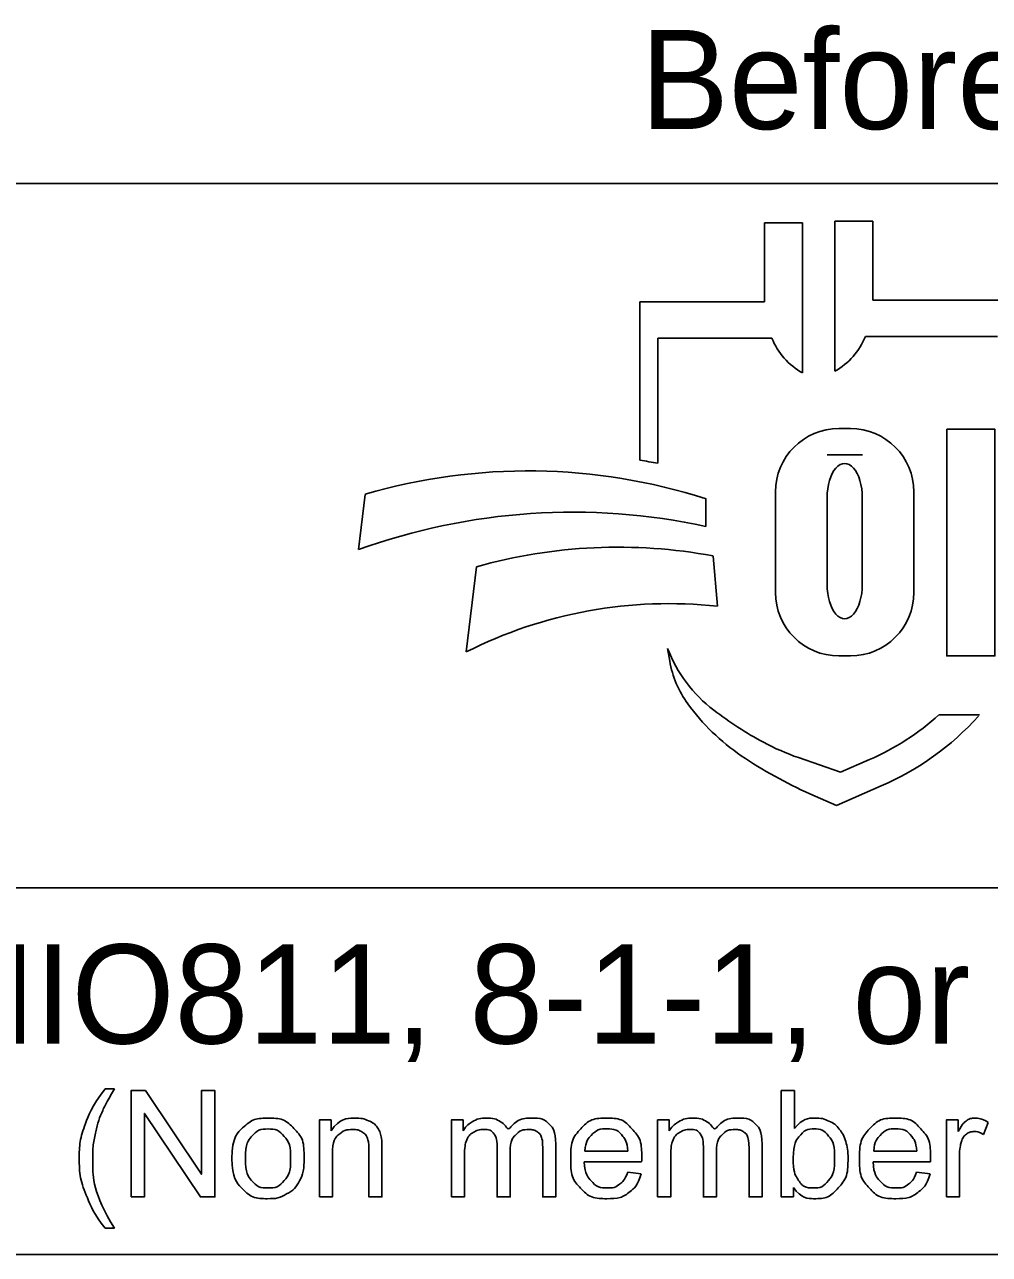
# Model space of a CAD drawing. Extents: x -7.5 to 26.5, y 3.5 to 25.5.
# Drawn here: x -4.768 to -3.406, y 5.643 to 7.38 of the extents above; entities that cross this region are included whole.
import ezdxf

# ---------------------------------------------------------------- set-up
doc = ezdxf.new("R2010")
doc.units = 0
doc.layers.add('SH_Data', color=7, linetype='Continuous')
doc.layers.add('SH_Text', color=7, linetype='Continuous')

msp = doc.modelspace()

# ---------------------------------------------------------------- linework, layer by layer
at = {"layer": 'SH_Data'}
for p, q in [((-5.0794, 7.1553), (-0.8294, 7.1553)), ((-0.8294, 6.1607), (-5.0794, 6.1607)), ((-0.8294, 5.6428), (-5.0794, 5.6428))]:
    msp.add_line(p, q, dxfattribs=at)
at = {"layer": 'SH_Text'}
for p, q in [((-3.7234, 6.9883), (-3.7234, 7.0998)), ((-3.7234, 7.0998), (-3.6698, 7.0998)), ((-3.6698, 7.0998), (-3.6698, 6.8877)), ((-3.6241, 6.89), (-3.6241, 7.1021)), ((-3.6241, 7.1021), (-3.5705, 7.1021)), ((-3.5705, 7.1021), (-3.5705, 6.9906)), ((-3.8994, 6.7644), (-3.8994, 6.9883)), ((-3.8994, 6.9883), (-3.7234, 6.9883)), ((-3.5705, 6.9906), (-3.3712, 6.9906)), ((-3.8741, 6.9369), (-3.8741, 6.76)), ((-3.713, 6.9369), (-3.8741, 6.9369)), ((-3.3945, 6.9392), (-3.5809, 6.9392)), ((-3.6184, 6.8091), (-3.6019, 6.8091)), ((-3.5851, 6.7721), (-3.6349, 6.7721)), ((-4.2967, 6.6381), (-4.2873, 6.7162)), ((-3.8061, 6.7097), (-3.8061, 6.6709)), ((-3.7079, 6.5776), (-3.7079, 6.7196)), ((-3.635, 6.589), (-3.635, 6.7114)), ((-3.5852, 6.7114), (-3.5852, 6.589)), ((-3.5124, 6.7196), (-3.5124, 6.5776)), ((-3.7961, 6.6291), (-3.7899, 6.5582)), ((-4.1449, 6.4936), (-4.1302, 6.6137)), ((-3.8572, 6.4807), (-3.8603, 6.4986)), ((-3.6019, 6.4882), (-3.6184, 6.4882)), ((-3.4769, 6.4048), (-3.4195, 6.4048)), ((-3.6753, 6.3444), (-3.6159, 6.3239)), ((-3.6159, 6.3239), (-3.5749, 6.3417)), ((-3.6219, 6.2769), (-3.6593, 6.2934)), ((-3.5587, 6.3044), (-3.6219, 6.2769))]:
    msp.add_line(p, q, dxfattribs=at)
msp.add_lwpolyline([(-3.466, 6.8081), (-3.398, 6.8081), (-3.398, 6.4881), (-3.466, 6.4881)], close=True, dxfattribs=at)
for points in [[(-4.6548, 5.8766), (-4.6416, 5.8766)], [(-4.6181, 5.7239), (-4.6181, 5.8741), (-4.5977, 5.8741), (-4.5187, 5.7561), (-4.5187, 5.8741), (-4.4997, 5.8741), (-4.4997, 5.7239), (-4.5201, 5.7239), (-4.5991, 5.8419), (-4.5991, 5.7239), (-4.6181, 5.7239)], [(-3.6826, 5.7239), (-3.6997, 5.7239), (-3.6997, 5.8741), (-3.6812, 5.8741), (-3.6812, 5.8206)], [(-4.3521, 5.7239), (-4.3521, 5.8328), (-4.3355, 5.8328), (-4.3355, 5.8173)], [(-4.1657, 5.7239), (-4.1657, 5.8328), (-4.1492, 5.8328), (-4.1492, 5.8174)], [(-3.8743, 5.7239), (-3.8743, 5.8328), (-3.8578, 5.8328), (-3.8578, 5.8174)], [(-3.4665, 5.7239), (-3.4665, 5.8328), (-3.4499, 5.8328), (-3.4499, 5.8163)], [(-3.4075, 5.8293), (-3.4139, 5.8122)], [(-4.2637, 5.7908), (-4.2637, 5.7239), (-4.2822, 5.7239), (-4.2822, 5.7901)], [(-4.0826, 5.7871), (-4.0826, 5.7239), (-4.101, 5.7239), (-4.101, 5.7946)], [(-4.0182, 5.7986), (-4.0182, 5.7239), (-4.0366, 5.7239), (-4.0366, 5.7924)], [(-3.9771, 5.7887), (-3.9163, 5.7887)], [(-3.7912, 5.7871), (-3.7912, 5.7239), (-3.8097, 5.7239), (-3.8097, 5.7946)], [(-3.7268, 5.7986), (-3.7268, 5.7239), (-3.7452, 5.7239), (-3.7452, 5.7924)], [(-3.5691, 5.7887), (-3.5083, 5.7887)], [(-4.3337, 5.7833), (-4.3337, 5.7239), (-4.3521, 5.7239)], [(-4.1473, 5.7803), (-4.1473, 5.7239), (-4.1657, 5.7239)], [(-3.8969, 5.7736), (-3.9781, 5.7736)], [(-3.8559, 5.7803), (-3.8559, 5.7239), (-3.8743, 5.7239)], [(-3.489, 5.7736), (-3.5701, 5.7736)], [(-3.4481, 5.7809), (-3.4481, 5.7239), (-3.4665, 5.7239)], [(-3.9165, 5.7591), (-3.8975, 5.7567)], [(-3.5085, 5.7591), (-3.4895, 5.7567)], [(-3.6826, 5.7375), (-3.6826, 5.7239)], [(-4.6416, 5.6798), (-4.6548, 5.6798)]]:
    msp.add_lwpolyline(points, dxfattribs=at)
for centre, radius, start, end in [((-3.6216, 6.9736), 0.0985, 201.9296, 240.7469), ((-3.6722, 6.976), 0.0985, 299.2531, 338.0704), ((-3.6184, 6.7196), 0.0895, 90, 180), ((-3.6019, 6.7196), 0.0895, 0, 90), ((-4.0275, 5.9554), 0.8191, 79.2074, 81.0007), ((-4.0572, 5.9302), 0.8191, 72.1402, 106.3144), ((-3.9942, 5.7991), 0.8919, 77.8238, 109.8274), ((-3.9303, 5.9094), 0.7322, 79.44, 105.8467), ((-3.6184, 6.5776), 0.0895, 180, 270), ((-3.6019, 6.5776), 0.0895, 270, 0), ((-3.8582, 5.9262), 0.6357, 83.8248, 116.8021), ((-3.6729, 6.5707), 0.2008, 201.0457, 232.5314), ((-3.7159, 6.5048), 0.1433, 189.6817, 216.0884), ((-3.5822, 6.6022), 0.3088, 216.0884, 235.7167), ((-3.4803, 6.8219), 0.5173, 232.5314, 241.794), ((-3.7183, 6.6722), 0.3602, 293.4582, 312.0712), ((-3.7183, 6.6722), 0.401, 293.4582, 317.8286), ((-3.5655, 6.6631), 0.3371, 241.794, 250.9821), ((-3.4157, 6.8465), 0.6044, 235.7167, 246.2325)]:
    msp.add_arc(centre, radius, start, end, dxfattribs=at)
for centre, start_param, end_param in [((-3.6101, 6.7114), 4.712389, 7.853982), ((-3.6101, 6.589), 1.570796, 4.712389)]:
    msp.add_ellipse(centre, major_axis=(0, 0.0484), ratio=0.514403, start_param=start_param, end_param=end_param, dxfattribs=at)
for points in [[(-4.6548, 5.6798), (-4.6701, 5.699), (-4.6806, 5.7248), (-4.6912, 5.7506), (-4.6912, 5.7783), (-4.6912, 5.8026), (-4.6833, 5.825), (-4.6741, 5.8509), (-4.6548, 5.8766)], [(-4.6416, 5.8766), (-4.654, 5.8553), (-4.658, 5.8462), (-4.6642, 5.832), (-4.6678, 5.8167), (-4.6722, 5.7975), (-4.6722, 5.7782), (-4.6722, 5.7289), (-4.6416, 5.6798)], [(-4.4756, 5.7783), (-4.4756, 5.8085), (-4.4588, 5.8231), (-4.4448, 5.8352), (-4.4246, 5.8352), (-4.4022, 5.8352), (-4.388, 5.8205), (-4.3737, 5.8058), (-4.3737, 5.7799), (-4.3737, 5.7589), (-4.38, 5.7469), (-4.3863, 5.7348), (-4.3983, 5.7282), (-4.4104, 5.7215), (-4.4246, 5.7215), (-4.4474, 5.7215), (-4.4615, 5.7362), (-4.4756, 5.7508), (-4.4756, 5.7783)], [(-4.4566, 5.7783), (-4.4566, 5.7574), (-4.4475, 5.747), (-4.4384, 5.7366), (-4.4246, 5.7366), (-4.4109, 5.7366), (-4.4018, 5.7471), (-4.3927, 5.7575), (-4.3927, 5.779), (-4.3927, 5.7991), (-4.4019, 5.8095), (-4.411, 5.8199), (-4.4246, 5.8199), (-4.4384, 5.8199), (-4.4475, 5.8096), (-4.4566, 5.7992), (-4.4566, 5.7783)], [(-4.3355, 5.8173), (-4.3235, 5.8352), (-4.3009, 5.8352), (-4.2911, 5.8352), (-4.2828, 5.8316), (-4.2746, 5.8281), (-4.2705, 5.8224), (-4.2664, 5.8166), (-4.2648, 5.8087), (-4.2637, 5.8036), (-4.2637, 5.7908)], [(-4.2822, 5.7901), (-4.2822, 5.8013), (-4.2843, 5.8069), (-4.2865, 5.8125), (-4.292, 5.8158), (-4.2974, 5.8191), (-4.3048, 5.8191), (-4.3166, 5.8191), (-4.3251, 5.8117), (-4.3337, 5.8042), (-4.3337, 5.7833)], [(-4.1492, 5.8174), (-4.1441, 5.8254), (-4.1356, 5.8303), (-4.1271, 5.8352), (-4.1162, 5.8352), (-4.1041, 5.8352), (-4.0964, 5.8301), (-4.0886, 5.8251), (-4.0855, 5.8161), (-4.0725, 5.8352), (-4.0518, 5.8352), (-4.0356, 5.8352), (-4.0269, 5.8262), (-4.0182, 5.8172), (-4.0182, 5.7986)], [(-4.101, 5.7946), (-4.101, 5.8069), (-4.1055, 5.813), (-4.1101, 5.8191), (-4.1203, 5.8191), (-4.1281, 5.8191), (-4.1347, 5.815), (-4.1413, 5.811), (-4.1443, 5.8031), (-4.1473, 5.7952), (-4.1473, 5.7803)], [(-4.0366, 5.7924), (-4.0366, 5.8035), (-4.0384, 5.8083), (-4.0402, 5.8132), (-4.0449, 5.8162), (-4.0496, 5.8191), (-4.056, 5.8191), (-4.0674, 5.8191), (-4.075, 5.8115), (-4.0826, 5.8039), (-4.0826, 5.7871)], [(-3.8975, 5.7567), (-3.902, 5.74), (-3.9141, 5.7307), (-3.9263, 5.7215), (-3.9453, 5.7215), (-3.9691, 5.7215), (-3.9831, 5.7362), (-3.9971, 5.7509), (-3.9971, 5.7774), (-3.9971, 5.8049), (-3.983, 5.82), (-3.9688, 5.8352), (-3.9463, 5.8352), (-3.9245, 5.8352), (-3.9107, 5.8203), (-3.8968, 5.8055), (-3.8968, 5.7785), (-3.8968, 5.7769), (-3.8969, 5.7736)], [(-3.9163, 5.7887), (-3.9175, 5.8025), (-3.9233, 5.8094), (-3.9321, 5.8201), (-3.9461, 5.8201), (-3.9588, 5.8201), (-3.9675, 5.8115), (-3.9761, 5.803), (-3.9771, 5.7887)], [(-3.8578, 5.8174), (-3.8527, 5.8254), (-3.8442, 5.8303), (-3.8357, 5.8352), (-3.8248, 5.8352), (-3.8127, 5.8352), (-3.805, 5.8301), (-3.7973, 5.8251), (-3.7941, 5.8161), (-3.7812, 5.8352), (-3.7604, 5.8352), (-3.7442, 5.8352), (-3.7355, 5.8262), (-3.7268, 5.8172), (-3.7268, 5.7986)], [(-3.8097, 5.7946), (-3.8097, 5.8069), (-3.8142, 5.813), (-3.8187, 5.8191), (-3.8289, 5.8191), (-3.8367, 5.8191), (-3.8433, 5.815), (-3.8499, 5.811), (-3.8529, 5.8031), (-3.8559, 5.7952), (-3.8559, 5.7803)], [(-3.7452, 5.7924), (-3.7452, 5.8035), (-3.747, 5.8083), (-3.7488, 5.8132), (-3.7535, 5.8162), (-3.7582, 5.8191), (-3.7646, 5.8191), (-3.7761, 5.8191), (-3.7836, 5.8115), (-3.7912, 5.8039), (-3.7912, 5.7871)], [(-3.6828, 5.7792), (-3.6828, 5.7596), (-3.6775, 5.7509), (-3.6688, 5.7366), (-3.654, 5.7366), (-3.6419, 5.7366), (-3.6331, 5.7471), (-3.6244, 5.7576), (-3.6244, 5.7784), (-3.6244, 5.7998), (-3.6328, 5.8099), (-3.6412, 5.8201), (-3.6532, 5.8201), (-3.6652, 5.8201), (-3.674, 5.8096), (-3.6828, 5.799), (-3.6828, 5.7792)], [(-3.6812, 5.8206), (-3.6696, 5.8352), (-3.6514, 5.8352), (-3.6414, 5.8352), (-3.6324, 5.8311), (-3.6235, 5.8271), (-3.6177, 5.8198), (-3.6119, 5.8124), (-3.6086, 5.8021), (-3.6054, 5.7918), (-3.6054, 5.78), (-3.6054, 5.752), (-3.6192, 5.7368), (-3.633, 5.7215), (-3.6524, 5.7215), (-3.6716, 5.7215), (-3.6826, 5.7375)], [(-3.4895, 5.7567), (-3.494, 5.74), (-3.5062, 5.7307), (-3.5183, 5.7215), (-3.5373, 5.7215), (-3.5611, 5.7215), (-3.5751, 5.7362), (-3.5891, 5.7509), (-3.5891, 5.7774), (-3.5891, 5.8049), (-3.575, 5.82), (-3.5608, 5.8352), (-3.5383, 5.8352), (-3.5165, 5.8352), (-3.5027, 5.8203), (-3.4889, 5.8055), (-3.4889, 5.7785), (-3.4889, 5.7769), (-3.489, 5.7736)], [(-3.5083, 5.7887), (-3.5095, 5.8025), (-3.5153, 5.8094), (-3.5241, 5.8201), (-3.5381, 5.8201), (-3.5508, 5.8201), (-3.5595, 5.8115), (-3.5682, 5.803), (-3.5691, 5.7887)], [(-3.4499, 5.8163), (-3.4436, 5.8278), (-3.4382, 5.8315), (-3.4329, 5.8352), (-3.4264, 5.8352), (-3.4171, 5.8352), (-3.4075, 5.8293)], [(-3.4139, 5.8122), (-3.4207, 5.8162), (-3.4274, 5.8162), (-3.4334, 5.8162), (-3.4382, 5.8125), (-3.443, 5.8089), (-3.445, 5.8024), (-3.4481, 5.7926), (-3.4481, 5.7809)], [(-3.9781, 5.7736), (-3.9771, 5.7557), (-3.968, 5.7462), (-3.9588, 5.7366), (-3.9452, 5.7366), (-3.9351, 5.7366), (-3.9279, 5.742), (-3.9207, 5.7473), (-3.9165, 5.7591)], [(-3.5701, 5.7736), (-3.5691, 5.7557), (-3.56, 5.7462), (-3.5508, 5.7366), (-3.5372, 5.7366), (-3.5271, 5.7366), (-3.5199, 5.742), (-3.5127, 5.7473), (-3.5085, 5.7591)]]:
    msp.add_open_spline(points, degree=3, dxfattribs=at)

# ---------------------------------------------------------------- texts
for s, p in [('Before You Dig', (-3.8986, 7.2321)), ('OHIO811, 8-1-1, or 1-800-362-2764', (-5.035, 5.9406))]:
    msp.add_text(s, height=0.14, dxfattribs=at).set_placement(p)

doc.saveas('drawing.dxf')
